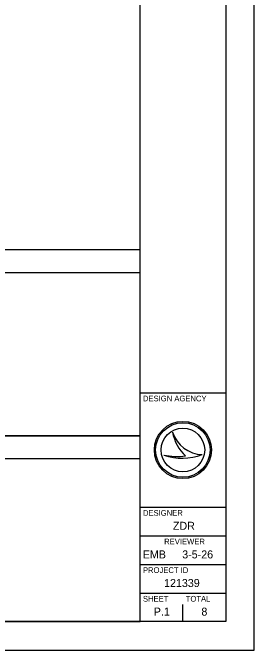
# Model space of a CAD drawing. Extents: x 0 to 34, y 0 to 22.
# Drawn here: x 29.77 to 34, y 0 to 11.14 of the extents above; entities that cross this region are included whole.
import ezdxf

# ---------------------------------------------------------------- set-up
doc = ezdxf.new("R2010")
doc.units = 0
for name, color, linetype in [('SH_Border', 7, 'Continuous'), ('SH_Cut_Line', 7, 'Continuous'), ('SH_Data', 7, 'Continuous')]:
    doc.layers.add(name, color=color, linetype=linetype)

msp = doc.modelspace()

# ---------------------------------------------------------------- linework, layer by layer
at = {"layer": 'SH_Border'}
for p, q in [((32, 0.5), (32, 21.5)), ((32, 4.5), (33.5, 4.5)), ((32, 2.5), (33.5, 2.5)), ((32, 2), (33.5, 2)), ((32, 1.5), (33.5, 1.5)), ((32, 1), (33.5, 1))]:
    msp.add_line(p, q, dxfattribs=at)
msp.add_lwpolyline([(1.5, 21.5), (33.5, 21.5), (33.5, 0.5), (1.5, 0.5)], close=True, dxfattribs=at)
at = {"layer": 'SH_Cut_Line'}
msp.add_lwpolyline([(0, 0), (34, 0), (34, 22), (0, 22)], close=True, dxfattribs=at)
at = {"layer": 'SH_Data'}
for p, q in [((29.2, 6.6), (32, 6.6)), ((32.567, 3.81), (32.567, 3.81)), ((32.75, 3.5), (32.75, 3.5)), ((29.2, 3.35), (32, 3.35)), ((32.417, 3.41), (32.417, 3.41)), ((33.087, 3.419), (33.087, 3.419)), ((32.75, 0.5), (32.75, 0.8)), ((32.375, 0.675), (32.375, 0.675))]:
    msp.add_line(p, q, dxfattribs=at)
for points in [[(32, 7), (29.2, 7), (29.2, 3.75), (32, 3.75)], [(32, 3.75), (29.2, 3.75), (29.2, 0.5), (32, 0.5)]]:
    msp.add_lwpolyline(points, close=True, dxfattribs=at)
for radius in [0.5, 0.477, 0.477, 0.382]:
    msp.add_circle((32.75, 3.5), radius, dxfattribs=at)
for centre, radius, start, end in [((33.116, 3.998), 0.58, 198.9257, 198.9319), ((33.347, 3.97), 0.796, 191.6379, 191.6421), ((33.116, 3.998), 0.58, 198.9319, 267.1657), ((33.347, 3.97), 0.796, 191.6421, 226.0947), ((32.739, 4.37), 1.013, 251.4576, 290.0832), ((32.648, 4.654), 1.266, 259.4964, 259.4995), ((32.739, 4.37), 1.013, 251.4527, 251.4576), ((32.648, 4.654), 1.266, 259.4995, 276.6672)]:
    msp.add_arc(centre, radius, start, end, dxfattribs=at)

# ---------------------------------------------------------------- texts
for s, height, p in [('DESIGN AGENCY', 0.1, (32.05, 4.35)), ('DESIGNER', 0.1, (32.05, 2.35)), ('ZDR', 0.14, (32.575, 2.105)), ('REVIEWER', 0.1, (32.422, 1.85)), ('EMB', 0.14, (32.047, 1.605)), ('3-5-26', 0.14, (32.738, 1.605)), ('PROJECT ID', 0.1, (32.05, 1.35)), ('121339', 0.14, (32.42, 1.105)), ('SHEET', 0.1, (32.05, 0.85)), ('TOTAL', 0.1, (32.8, 0.85)), ('P.1', 0.14, (32.24, 0.605)), ('8', 0.14, (33.074, 0.605))]:
    msp.add_text(s, height=height, dxfattribs=at).set_placement(p)

doc.saveas('drawing.dxf')
